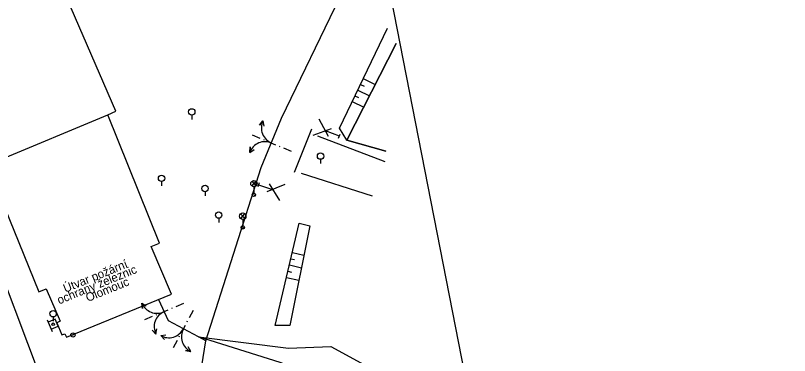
# Model space of a CAD drawing. Extents: x -545736 to -544888, y -1122892 to -1119128.
# Drawn here: x -545179.4 to -545088.3, y -1121612.1 to -1121572.1 of the extents above; entities that cross this region are included whole.
import ezdxf

# ---------------------------------------------------------------- set-up
doc = ezdxf.new("R2010")
doc.units = 0
for name, color, linetype in [('Vrstva 1', 7, 'Continuous'), ('Vrstva 10', 7, 'Continuous'), ('Vrstva 17', 7, 'Continuous'), ('Vrstva 23', 7, 'Continuous'), ('Vrstva 25', 7, 'Continuous'), ('Vrstva 28', 7, 'Continuous'), ('Vrstva 3', 7, 'Continuous'), ('Vrstva 36', 7, 'Continuous'), ('Vrstva 4', 7, 'Continuous'), ('Vrstva 48', 7, 'Continuous'), ('Vrstva 49', 7, 'Continuous'), ('Vrstva 51', 7, 'Continuous')]:
    doc.layers.add(name, color=color, linetype=linetype)

msp = doc.modelspace()

# ---------------------------------------------------------------- linework, layer by layer
at = {"layer": 'Vrstva 1'}
msp.add_lwpolyline([(-545218.327, -1121512.169), (-545215.614, -1121518.744), (-545202.659, -1121550.017), (-545195.247, -1121567.92), (-545182.766, -1121598.165), (-545176.378, -1121614.965), (-545172.622, -1121626.586), (-545169.798, -1121637.37), (-545165.151, -1121654.745)], dxfattribs=at)
at = {"layer": 'Vrstva 10'}
msp.add_line((-545169.988, -1121392.291), (-544887.573, -1122835.274), dxfattribs=at)
at = {"layer": 'Vrstva 17'}
for p, q in [((-545148.099, -1121584.224), (-545140.036, -1121567.529)), ((-545150.29, -1121584.538), (-545150.706, -1121585.015)), ((-545150.508, -1121589.997), (-545148.099, -1121584.224)), ((-545151.568, -1121586.172), (-545150.645, -1121586.557)), ((-545150.23, -1121586.731), (-545150.138, -1121586.769)), ((-545149.722, -1121586.942), (-545148.8, -1121587.328)), ((-545151.831, -1121588.23), (-545151.784, -1121587.599)), ((-545148.384, -1121587.501), (-545148.292, -1121587.539)), ((-545147.877, -1121587.713), (-545146.954, -1121588.098)), ((-545156.992, -1121610.425), (-545150.508, -1121589.997)), ((-545161.393, -1121608.074), (-545162.522, -1121605.588)), ((-545164.54, -1121605.967), (-545164.474, -1121606.596)), ((-545159.632, -1121606.016), (-545160.555, -1121606.402)), ((-545162.814, -1121607.349), (-545162.906, -1121607.388)), ((-545161.477, -1121606.789), (-545162.399, -1121607.175)), ((-545160.97, -1121606.576), (-545161.062, -1121606.615)), ((-545158.939, -1121607.672), (-545158.47, -1121606.789)), ((-545163.321, -1121607.562), (-545164.244, -1121607.948)), ((-545157.88, -1121609.939), (-545161.393, -1121608.074)), ((-545159.197, -1121608.158), (-545159.15, -1121608.07)), ((-545162.886, -1121609.609), (-545163.317, -1121609.146)), ((-545159.876, -1121609.439), (-545159.408, -1121608.555)), ((-545162.323, -1121609.782), (-545161.887, -1121610.24)), ((-545160.134, -1121609.924), (-545160.087, -1121609.836)), ((-545160.814, -1121611.205), (-545160.345, -1121610.322)), ((-545158.79, -1121611.657), (-545159.414, -1121611.552))]:
    msp.add_line(p, q, dxfattribs=at)
for points in [[(-545134.604, -1121575.41), (-545140.405, -1121586.789), (-545135.82, -1121588.083)], [(-545150.706, -1121585.015), (-545150.29, -1121584.538), (-545150.16, -1121585.135)], [(-545151.784, -1121587.599), (-545151.831, -1121588.23), (-545151.315, -1121587.903)], [(-545164.474, -1121606.596), (-545164.54, -1121605.967), (-545164.015, -1121606.278)], [(-545163.317, -1121609.146), (-545162.886, -1121609.609), (-545162.775, -1121609.009)], [(-545161.887, -1121610.24), (-545162.323, -1121609.782), (-545161.717, -1121609.707)], [(-545149.838, -1121645.646), (-545152.748, -1121645.794), (-545156.047, -1121645.894), (-545159.498, -1121646.03), (-545162.062, -1121646.037), (-545160.791, -1121633.913), (-545156.992, -1121610.425), (-545157.88, -1121609.939)], [(-545159.414, -1121611.552), (-545158.79, -1121611.657), (-545159.067, -1121611.114)]]:
    msp.add_lwpolyline(points, dxfattribs=at)
for centre, start, end in [((-545148.555, -1121585.353), 154.86467, 248.38456), ((-545150.031, -1121588.891), 66.31512, 159.835), ((-545162.762, -1121605.251), 201.93969, 295.45957), ((-545161.177, -1121608.742), 113.39013, 206.91001), ((-545161.351, -1121608.129), 239.55166, 333.07154), ((-545157.965, -1121609.926), 151.00211, 244.52199)]:
    msp.add_arc(centre, 1.917, start, end, dxfattribs=at)
at = {"layer": 'Vrstva 23'}
msp.add_line((-545182.632, -1121589.687), (-545168.549, -1121583.825), dxfattribs=at)
for points in [[(-545163.43, -1121599.323), (-545162.461, -1121598.907), (-545168.549, -1121583.825), (-545167.585, -1121583.378), (-545173.378, -1121570.042), (-545193.53, -1121520.81), (-545196.125, -1121513.956), (-545200.025, -1121504.563), (-545201.914, -1121500.208), (-545214.824, -1121505.578), (-545215.505, -1121504.469), (-545216.906, -1121505.087), (-545216.548, -1121506.16), (-545216.91, -1121506.413), (-545199.14, -1121549.483)], [(-545199.14, -1121549.483), (-545184.544, -1121584.902), (-545183.89, -1121586.523), (-545182.632, -1121589.687), (-545182.389, -1121590.284), (-545182.528, -1121590.341), (-545176.667, -1121604.641), (-545175.784, -1121604.295)], [(-545175.784, -1121604.295), (-545175.784, -1121604.295), (-545174.17, -1121608.104), (-545174.556, -1121608.298), (-545173.972, -1121609.693), (-545173.606, -1121609.579), (-545173.416, -1121609.965), (-545161.034, -1121604.934), (-545163.43, -1121599.323)]]:
    msp.add_lwpolyline(points, dxfattribs=at)
at = {"layer": 'Vrstva 25'}
for p, q in [((-545151.59, -1121591.636), (-545151.093, -1121592.191)), ((-545151.583, -1121592.201), (-545151.091, -1121591.64)), ((-545151.343, -1121592.289), (-545151.343, -1121593.039)), ((-545151.537, -1121593.279), (-545151.303, -1121593.045)), ((-545151.404, -1121593.427), (-545151.154, -1121593.177)), ((-545152.906, -1121595.461), (-545152.409, -1121596.016)), ((-545152.899, -1121596.025), (-545152.407, -1121595.465)), ((-545152.659, -1121596.114), (-545152.659, -1121596.864)), ((-545152.853, -1121597.104), (-545152.619, -1121596.87)), ((-545152.72, -1121597.252), (-545152.47, -1121597.002))]:
    msp.add_line(p, q, dxfattribs=at)
for centre, radius in [((-545151.345, -1121591.915), 0.374), ((-545151.343, -1121593.239), 0.2), ((-545151.343, -1121593.239), 0.2), ((-545152.66, -1121595.74), 0.374), ((-545152.659, -1121597.064), 0.2), ((-545152.659, -1121597.064), 0.2)]:
    msp.add_circle(centre, radius, dxfattribs=at)
at = {"layer": 'Vrstva 28'}
msp.add_line((-545172.673, -1121609.723), (-545172.623, -1121609.723), dxfattribs=at)
msp.add_circle((-545172.648, -1121609.723), 0.25, dxfattribs=at)
at = {"layer": 'Vrstva 3'}
for p, q in [((-545175.674, -1121607.947), (-545175.098, -1121609.307)), ((-545174.742, -1121607.873), (-545175.559, -1121608.219)), ((-545175.559, -1121608.219), (-545175.213, -1121609.035)), ((-545174.396, -1121608.689), (-545174.742, -1121607.873)), ((-545175.213, -1121609.035), (-545174.396, -1121608.689))]:
    msp.add_line(p, q, dxfattribs=at)
msp.add_circle((-545174.977, -1121608.455), 0.148, dxfattribs=at)
at = {"layer": 'Vrstva 36'}
for p, q in [((-545158.665, -1121583.85), (-545158.664, -1121584.35)), ((-545143.499, -1121589.049), (-545143.498, -1121589.549)), ((-545162.217, -1121591.664), (-545162.216, -1121592.164)), ((-545157.102, -1121592.86), (-545157.101, -1121593.36)), ((-545155.491, -1121595.988), (-545155.49, -1121596.488)), ((-545174.983, -1121607.597), (-545174.982, -1121608.097))]:
    msp.add_line(p, q, dxfattribs=at)
for centre in [(-545158.665, -1121583.471), (-545143.499, -1121588.671), (-545162.217, -1121591.285), (-545157.102, -1121592.482), (-545155.491, -1121595.609), (-545174.983, -1121607.219)]:
    msp.add_circle(centre, 0.378, dxfattribs=at)
at = {"layer": 'Vrstva 4'}
for p, q in [((-545142.564, -1121586.37), (-545143.659, -1121584.342)), ((-545144.58, -1121585.497), (-545146.593, -1121590.605)), ((-545144.377, -1121586.209), (-545142.205, -1121585.437)), ((-545141.288, -1121586.325), (-545142.921, -1121585.697)), ((-545141.378, -1121586.558), (-545141.198, -1121586.092)), ((-545150.731, -1121591.817), (-545150.883, -1121592.293)), ((-545149.535, -1121591.937), (-545148.326, -1121593.9)), ((-545150.807, -1121592.055), (-545149.14, -1121592.589)), ((-545147.716, -1121591.995), (-545149.84, -1121592.89))]:
    msp.add_line(p, q, dxfattribs=at)
at = {"layer": 'Vrstva 48'}
for p, q in [((-545138.478, -1121579.552), (-545137.062, -1121580.232)), ((-545139.128, -1121580.904), (-545137.744, -1121581.569)), ((-545138.803, -1121580.228), (-545138.383, -1121580.43)), ((-545139.453, -1121581.58), (-545139.042, -1121581.777)), ((-545139.777, -1121582.256), (-545138.425, -1121582.906)), ((-545146.824, -1121600.019), (-545145.46, -1121600.342)), ((-545146.997, -1121600.749), (-545146.58, -1121600.847)), ((-545147.169, -1121601.478), (-545145.757, -1121601.813)), ((-545147.342, -1121602.208), (-545146.911, -1121602.31)), ((-545147.515, -1121602.938), (-545146.054, -1121603.284))]:
    msp.add_line(p, q, dxfattribs=at)
at = {"layer": 'Vrstva 49'}
msp.add_line((-545140.405, -1121586.789), (-545134.604, -1121575.41), dxfattribs=at)
for points in [[(-545135.82, -1121588.083), (-545140.405, -1121586.789), (-545141.277, -1121585.379), (-545135.633, -1121573.628)], [(-545148.858, -1121608.612), (-545146.002, -1121596.546)], [(-545146.002, -1121596.546), (-545144.758, -1121596.87), (-545147.132, -1121608.617), (-545148.858, -1121608.612)], [(-545157.88, -1121609.939), (-545147.278, -1121611.253), (-545142.301, -1121611.093), (-545132.728, -1121616.281), (-545134.742, -1121623.544), (-545138.347, -1121640.519), (-545143.84, -1121651.319)], [(-545143.84, -1121651.319), (-545144.274, -1121648.865), (-545141.256, -1121639.713), (-545141.36, -1121636.527), (-545137.511, -1121624.217), (-545136.054, -1121618.085), (-545142.343, -1121615.227), (-545148.248, -1121612.972), (-545157.88, -1121609.939)]]:
    msp.add_lwpolyline(points, dxfattribs=at)
at = {"layer": 'Vrstva 51'}
for p, q in [((-545135.913, -1121589.354), (-545143.837, -1121586.307)), ((-545135.913, -1121589.354), (-545143.837, -1121586.307)), ((-545137.406, -1121593.373), (-545145.727, -1121590.708))]:
    msp.add_line(p, q, dxfattribs=at)

# ---------------------------------------------------------------- texts
at = {"layer": 'Vrstva 23'}
for s, p in [('Útvar požární', (-545173.545, -1121604.762)), ('ochrany železnic', (-545174.265, -1121606.134)), ('Olomouc', (-545170.902, -1121605.847))]:
    msp.add_text(s, height=1, rotation=22.11268, dxfattribs=at).set_placement(p)

doc.saveas('drawing.dxf')
